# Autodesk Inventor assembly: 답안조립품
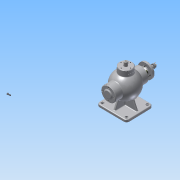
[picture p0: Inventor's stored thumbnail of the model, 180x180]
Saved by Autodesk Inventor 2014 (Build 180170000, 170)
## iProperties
Created: 2017-01
Part Number: 답안조립품
Document SubType Name: Assembly
Designer: ksu
Author: ksu
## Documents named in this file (19)
- C:\Users\ksu\Desktop\470118V1014\답안조립품.iam
- C:\Users\ksu\Desktop\470118V1014\1본체.ipt
- C:\Users\ksu\Desktop\470118V1014\V-벨트풀리.ipt
- C:\Users\ksu\Desktop\470118V1014\너트 M8.ipt
- C:\Users\ksu\Desktop\470118V1014\뒤커버.ipt
- C:\Users\ksu\Desktop\470118V1014\멈춤링- 15 x 1.ipt
- C:\Users\ksu\Desktop\470118V1014\멈춤링- 35x1.6.ipt
- KS B 1336 - 35x1.6.ipt
- C:\Users\ksu\Desktop\470118V1014\베어링- 6202.ipt
- KS B 2023 - 6202 - 15 x 35 x 11 - 7.8.ipt
- C:\Users\ksu\Desktop\470118V1014\볼트 M4 x 12.ipt
- C:\Users\ksu\Desktop\470118V1014\볼트 M4 x 16.ipt
- C:\Users\ksu\Desktop\470118V1014\부시.ipt
- C:\Users\ksu\Desktop\470118V1014\상부커버.ipt
- C:\Users\ksu\Desktop\470118V1014\슬라이드.ipt
- C:\Users\ksu\Desktop\470118V1014\앞커버.ipt
- C:\Users\ksu\Desktop\470118V1014\오일실 15 30 7.ipt
- C:\Users\ksu\Desktop\470118V1014\키 4 x 4 x 12.ipt
- C:\Users\ksu\Desktop\470118V1014\편심축.ipt
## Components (14 placed, 6 different names)
1. 1본체:1 — Mate:11, Mate:13, Mate:14, Mate:15, Mate:16, Mate:17, Mate:18, Mate:20
2. V-벨트풀리:1 — Mate:2, Mate:3, Flush:1
3. KS B 1336 - 35x1.6:1 — Mate:4, Mate:7
4. KS B 2023 - 6202 - 15 x 35 x 11 - 7.8:1 — Insert:3, Insert:5
5. KS B 1021 - 에 따름 ISO 1207 - 미터 A  M 4 x 12:1
6. KS B 2023 - 6202 - 15 x 35 x 11 - 7.8:2 — Mate:4, Mate:5, Mate:6, Mate:7, Mate:8, Mate:10
7. ISO 4762 M4 x 16:2 — Insert:7
8. ISO 4762 M4 x 16:3
9. ISO 4762 M4 x 16:4
10. ISO 4762 M4 x 16:5
11. ISO 4762 M4 x 16:1 — Insert:8
12. ISO 4762 M4 x 16:6
13. ISO 4762 M4 x 16:7
14. ISO 4762 M4 x 16:8
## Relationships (21: Mate 16, Insert 4, Flush 1)
- Mate:2: V-벨트풀리:1
- Mate:3: V-벨트풀리:1
- Flush:1: V-벨트풀리:1
- Insert:3: KS B 2023 - 6202 - 15 x 35 x 11 - 7.8:1
- Insert:5: KS B 2023 - 6202 - 15 x 35 x 11 - 7.8:1
- Mate:4: KS B 1336 - 35x1.6:1 ↔ KS B 2023 - 6202 - 15 x 35 x 11 - 7.8:2
- Mate:5: KS B 2023 - 6202 - 15 x 35 x 11 - 7.8:2
- Mate:6: KS B 2023 - 6202 - 15 x 35 x 11 - 7.8:2
- Mate:7: KS B 1336 - 35x1.6:1 ↔ KS B 2023 - 6202 - 15 x 35 x 11 - 7.8:2
- Mate:8: KS B 2023 - 6202 - 15 x 35 x 11 - 7.8:2
- Mate:10: KS B 2023 - 6202 - 15 x 35 x 11 - 7.8:2
- Mate:11: 1본체:1
- Mate:13: 1본체:1
- Mate:14: 1본체:1
- Mate:15: 1본체:1
- Mate:16: 1본체:1
- Mate:17: 1본체:1
- Mate:18: 1본체:1
- Insert:7: ISO 4762 M4 x 16:2
- Mate:20: 1본체:1
- Insert:8: ISO 4762 M4 x 16:1
